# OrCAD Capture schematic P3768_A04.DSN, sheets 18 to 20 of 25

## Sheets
18 0007_DC JACK: size Custom
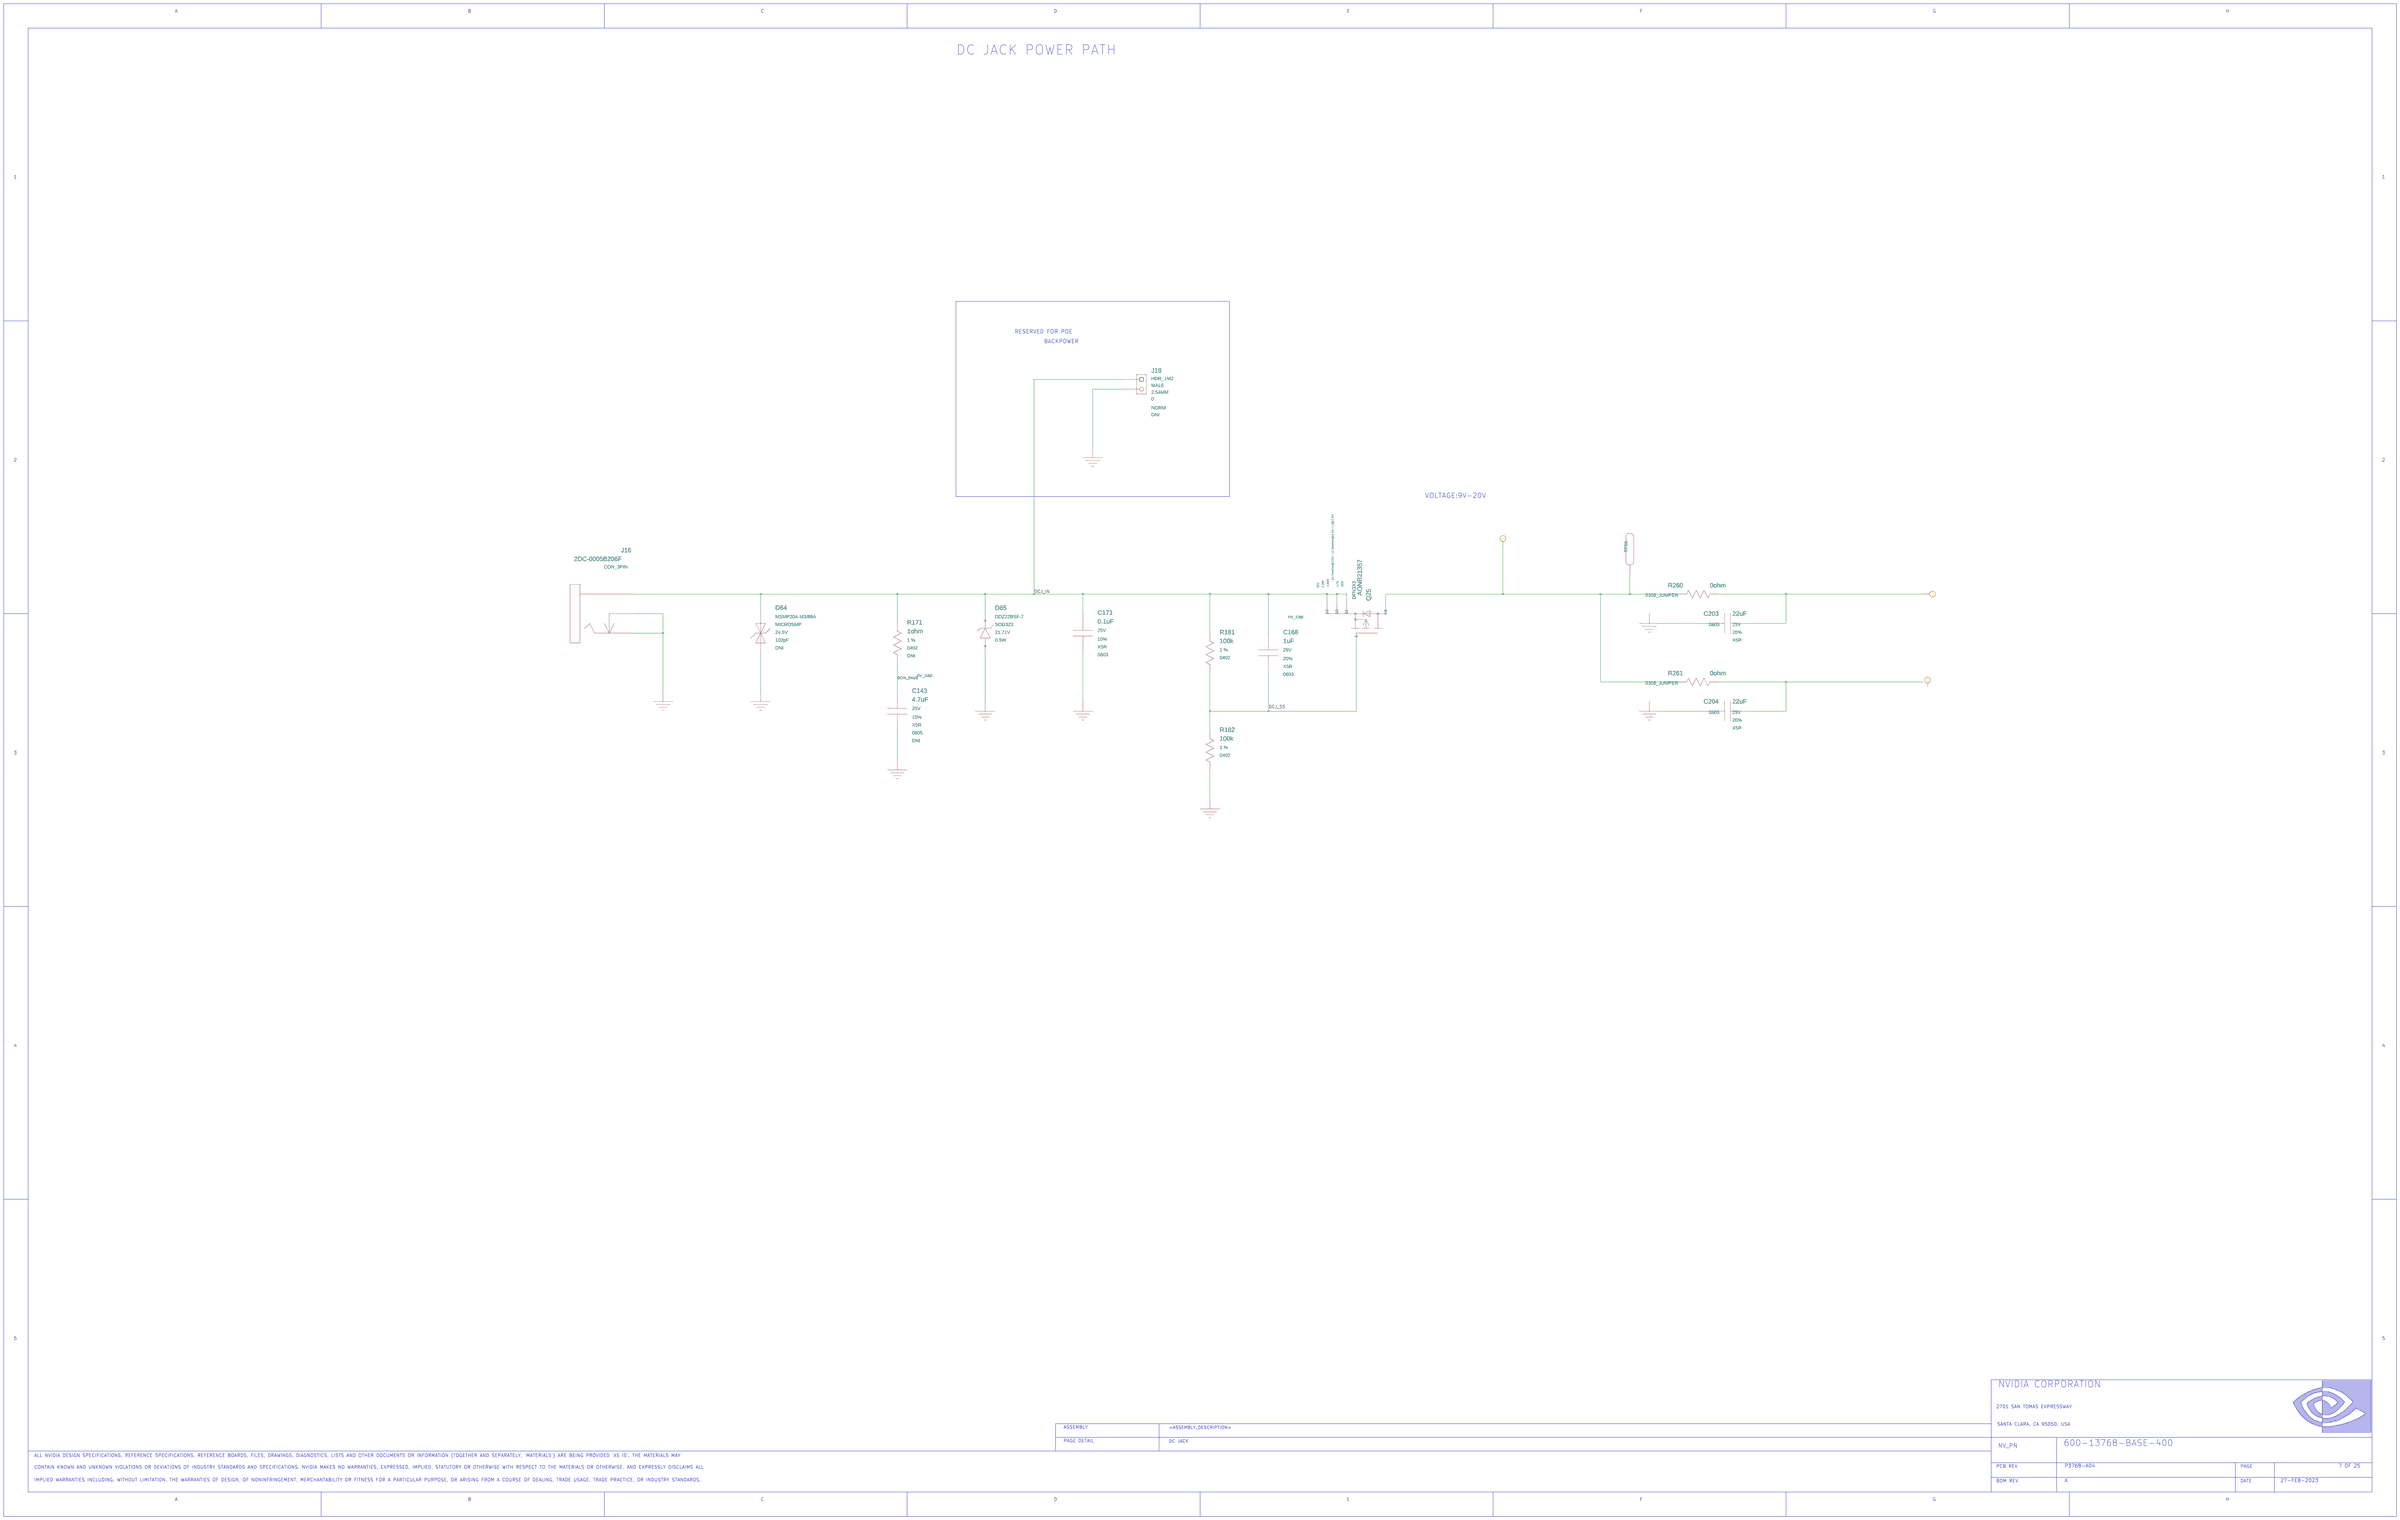
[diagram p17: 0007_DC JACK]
19 0006_SODIMM Connector 3_3: size Custom
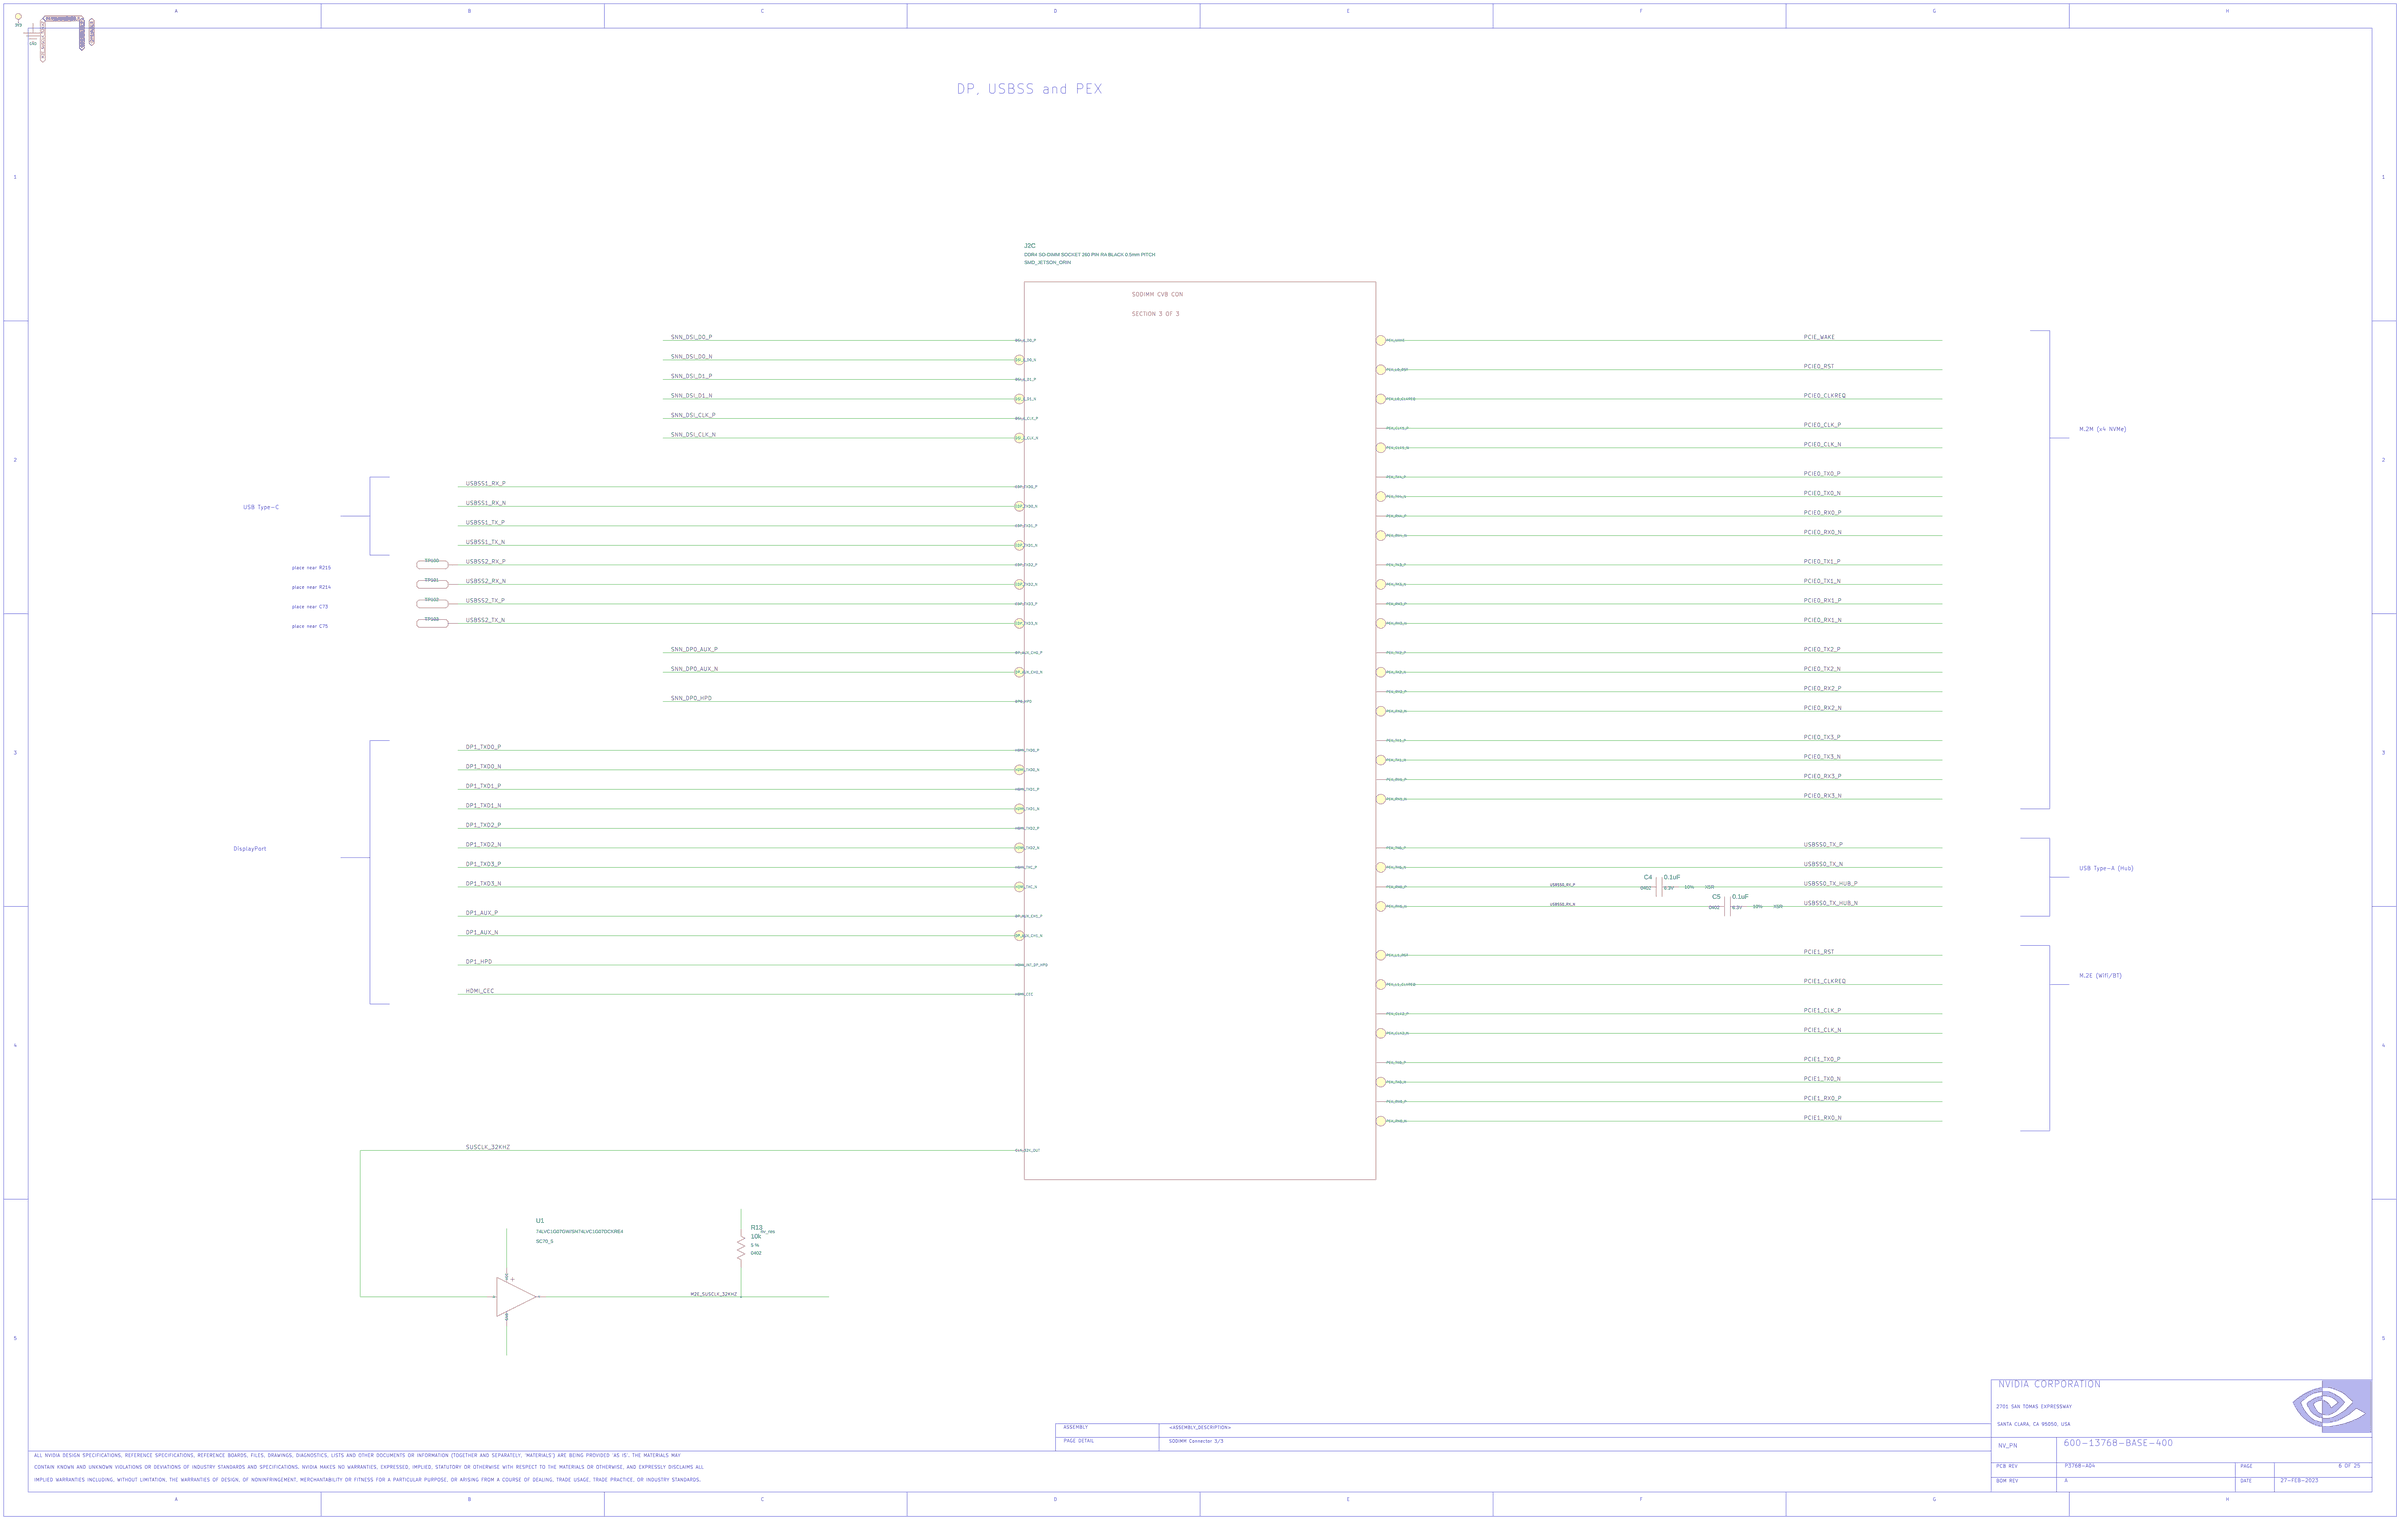
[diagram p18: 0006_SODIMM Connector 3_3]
20 0005_SODIMM Connector 2_3: size Custom
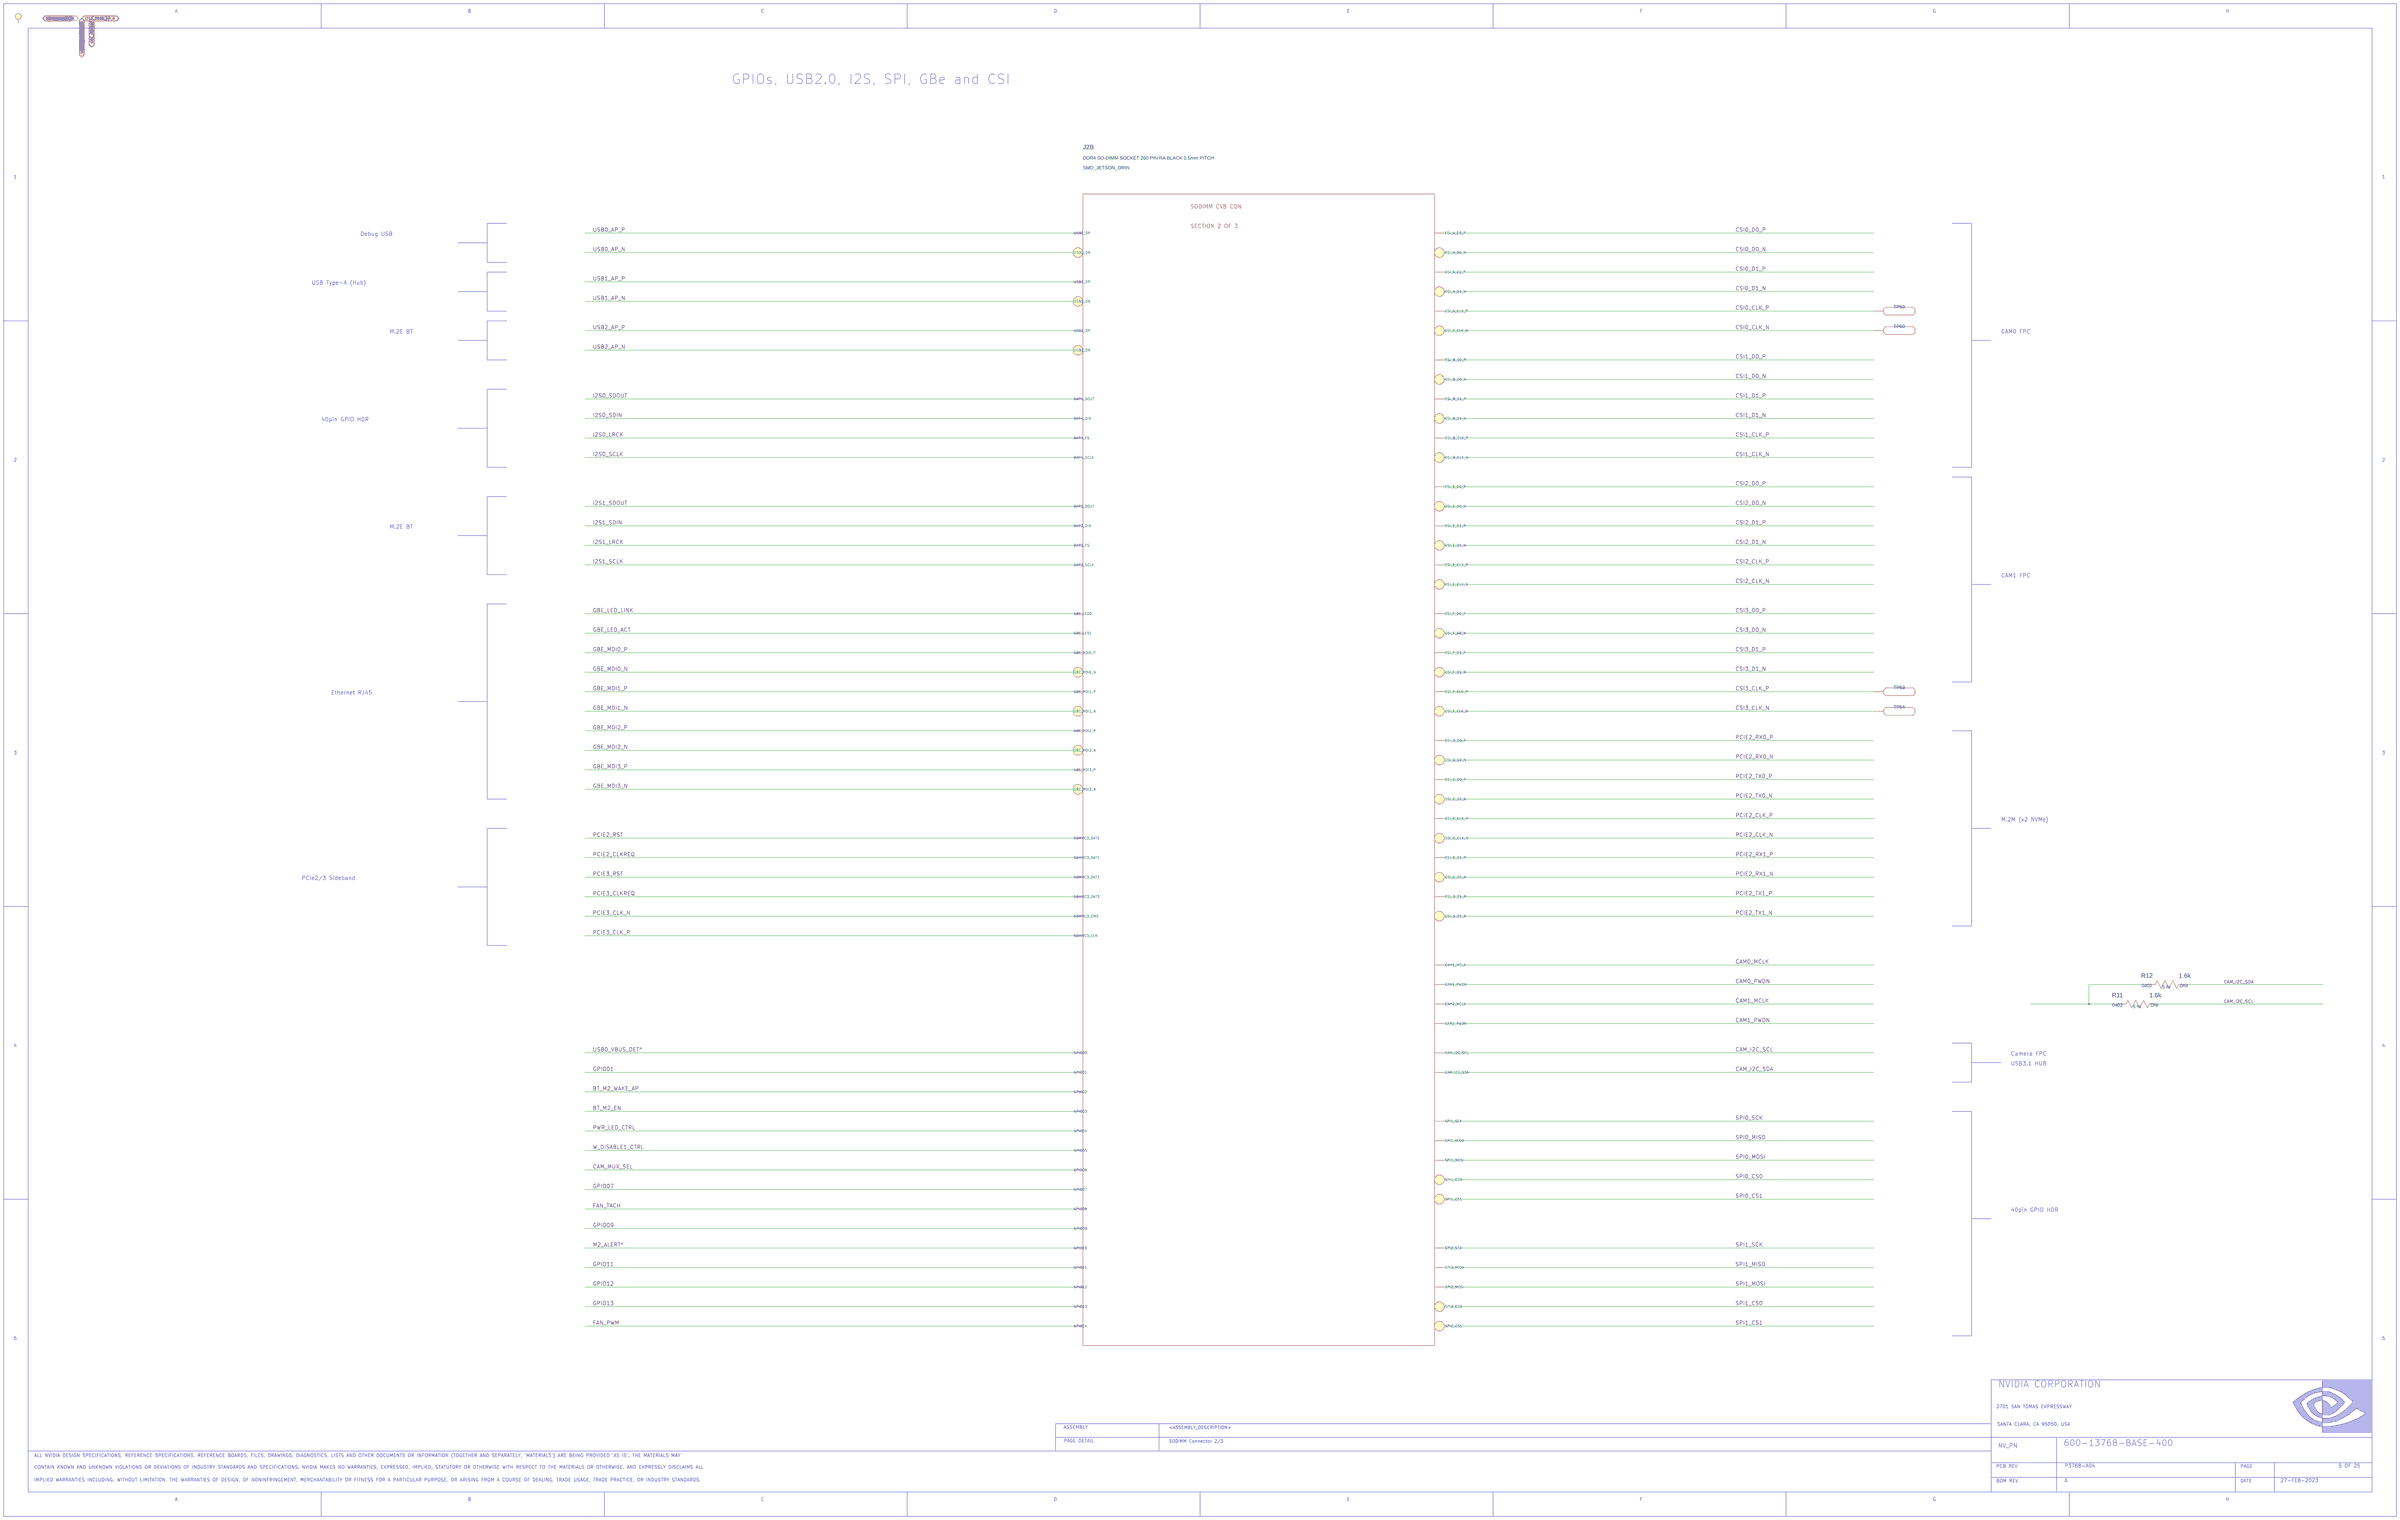
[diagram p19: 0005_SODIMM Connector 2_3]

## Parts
sheet 0005_SODIMM Connector 2_3
R11  1.6k  [0402]
R12  1.6k  [0402]
TP53  LABTESTPOINT  [LTPT025C]
TP54  LABTESTPOINT  [LTPT025C]
TP59  LABTESTPOINT  [LTPT025C]
TP60  LABTESTPOINT  [LTPT025C]
sheet 0006_SODIMM Connector 3_3
C4  0.1uF  [0402]
C5  0.1uF  [0402]
J2  CON_SODIMM_260  [CON_SODIMM_260_SMT_RA_F_P005]  (sections A,B,C)
R13  10k  [0402]
TP100  LABTESTPOINT  [LTPT025C]
TP101  LABTESTPOINT  [LTPT025C]
TP102  LABTESTPOINT  [LTPT025C]
TP103  LABTESTPOINT  [LTPT025C]
U1  U_BUF_OD  [SC70_5]
sheet 0007_DC JACK
C143  4.7uF  [0805U]
C168  1uF  [0603]
C171  0.1uF  [0603]
C203  22uF  [0805U]
C204  22uF  [0805U]
D64  D_ESD  [DIODE_SMD_025X013]
D65  D_ZENER  [DIODE_SMD_SOD323_C]
J16  CON_PWR_JACK  [CON_PWR_003_TH_RA_145X090_C]
J18  HDR_1X2  [CON_HDR_001X002_TH_ST_M_P025]
Q25  Q_FET_P_ENH  [DFET_SMD_032X033]
R171  1ohm  [0402]
R181  100k  [0402]
R182  100k  [0402]
R260  0ohm  [0603_BROADWISE_SHORT]
R261  0ohm  [0603_BROADWISE_SHORT]
TP56  LABTESTPOINT  [LTPT071C125D]

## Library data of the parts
R11 = R#1: ASSEMBLY: CVB_CONN; CDS_LIB: discrete; CDS_PART_NAME: R_0402-1.6K,5 %,62.5MW,195-0521-000; CDS_PHYS_PART_NAME: R_0402-1.6K,5 %,62.5MW,195-0521-000-1.6K,195-0521-000; CDS_SEC: 1; CHIPS_PART_NAME: R; DEVICE_TYPENAME: R_0402-16K5625MW195-0521-000-16K195-0521-000; DRAWING: @P3768_A04_LIB.P3768_A04(SCH_1):PAGE5; MAX_WATTAGE: 62.5mW; NV_PN: 195-0521-000; PATH: I130; PHYS_PAGE: 5; PSPICETEMPLATE: X^@REFDES  %1    %2   @NV_PN; ROT: 0; SEC: 1; SIGNAL_MODEL: nv_res; SKU: DNI; TOL: 5 %; VER: 1; XY: (-1200,2500)
R12 = R#1: ASSEMBLY: CVB_CONN; CDS_LIB: discrete; CDS_PART_NAME: R_0402-1.6K,5 %,62.5MW,195-0521-000; CDS_PHYS_PART_NAME: R_0402-1.6K,5 %,62.5MW,195-0521-000-1.6K,195-0521-000; CDS_SEC: 1; CHIPS_PART_NAME: R; DEVICE_TYPENAME: R_0402-16K5625MW195-0521-000-16K195-0521-000; DRAWING: @P3768_A04_LIB.P3768_A04(SCH_1):PAGE5; MAX_WATTAGE: 62.5mW; NV_PN: 195-0521-000; PATH: I129; PHYS_PAGE: 5; PSPICETEMPLATE: X^@REFDES  %1    %2   @NV_PN; ROT: 0; SEC: 1; SIGNAL_MODEL: nv_res; SKU: DNI; TOL: 5 %; VER: 1; XY: (-1050,2600)
TP53 = LABTESTPOINT: CDS_LIB: electro_mechanic; CDS_PART_NAME: LABTESTPOINT_PIN-TESTPOINT_0.25MM; CDS_PHYS_PART_NAME: LABTESTPOINT_PIN-TESTPOINT_0.25MM; CDS_SEC: 1; DEVICE_TYPENAME: LABTESTPOINT_PIN-TESTPOINT_025MM; DRAWING: @P3768_A04_LIB.P3768_A04(SCH_1):PAGE5; NV_NAME: TESTPOINT_0.25mm; PACK_TYPE: PIN; PATH: I246; PHYS_PAGE: 5; ROT: 0; SEC: 1; VER: 3; XY: (-2500,4100)
TP54 = LABTESTPOINT: CDS_LIB: electro_mechanic; CDS_PART_NAME: LABTESTPOINT_PIN-TESTPOINT_0.25MM; CDS_PHYS_PART_NAME: LABTESTPOINT_PIN-TESTPOINT_0.25MM; CDS_SEC: 1; DEVICE_TYPENAME: LABTESTPOINT_PIN-TESTPOINT_025MM; DRAWING: @P3768_A04_LIB.P3768_A04(SCH_1):PAGE5; NV_NAME: TESTPOINT_0.25mm; PACK_TYPE: PIN; PATH: I247; PHYS_PAGE: 5; ROT: 0; SEC: 1; VER: 3; XY: (-2500,4000)
TP59 = LABTESTPOINT: CDS_LIB: electro_mechanic; CDS_PART_NAME: LABTESTPOINT_PIN-TESTPOINT_0.25MM; CDS_PHYS_PART_NAME: LABTESTPOINT_PIN-TESTPOINT_0.25MM; CDS_SEC: 1; DEVICE_TYPENAME: LABTESTPOINT_PIN-TESTPOINT_025MM; DRAWING: @P3768_A04_LIB.P3768_A04(SCH_1):PAGE5; NV_NAME: TESTPOINT_0.25mm; PACK_TYPE: PIN; PATH: I248; PHYS_PAGE: 5; ROT: 0; SEC: 1; VER: 3; XY: (-2500,6050)
TP60 = LABTESTPOINT: CDS_LIB: electro_mechanic; CDS_PART_NAME: LABTESTPOINT_PIN-TESTPOINT_0.25MM; CDS_PHYS_PART_NAME: LABTESTPOINT_PIN-TESTPOINT_0.25MM; CDS_SEC: 1; DEVICE_TYPENAME: LABTESTPOINT_PIN-TESTPOINT_025MM; DRAWING: @P3768_A04_LIB.P3768_A04(SCH_1):PAGE5; NV_NAME: TESTPOINT_0.25mm; PACK_TYPE: PIN; PATH: I249; PHYS_PAGE: 5; ROT: 0; SEC: 1; VER: 3; XY: (-2500,5950)
C4 = C: ASSEMBLY: CVB_CONN; CDS_LIB: discrete; CDS_PART_NAME: C_0402-0.1UF,X5R,10%,6.3V,039-0007-000; CDS_PHYS_PART_NAME: C_0402-0.1UF,X5R,10%,6.3V,039-0007-000-0.1UF,039-0007-000; CDS_SEC: 1; DEVICE_TYPENAME: C_0402-01UFX5R1063V039-0007-000-01UF039-0007-000; DRAWING: @P3768_A04_LIB.P3768_A04(SCH_1):PAGE6; MAT: X5R; MAX_VOLTAGE: 6.3V; NV_PN: 039-0007-000; PATH: I36; PHYS_PAGE: 6; PSPICETEMPLATE: X^@REFDES  %1    %2   @NV_PN; ROT: 0; SEC: 1; SIGNAL_MODEL: nv_cap; TOL: 10%; VER: 2; XY: (-3650,3100)
C5 = C: ASSEMBLY: CVB_CONN; CDS_LIB: discrete; CDS_PART_NAME: C_0402-0.1UF,X5R,10%,6.3V,039-0007-000; CDS_PHYS_PART_NAME: C_0402-0.1UF,X5R,10%,6.3V,039-0007-000-0.1UF,039-0007-000; CDS_SEC: 1; DEVICE_TYPENAME: C_0402-01UFX5R1063V039-0007-000-01UF039-0007-000; DRAWING: @P3768_A04_LIB.P3768_A04(SCH_1):PAGE6; MAT: X5R; MAX_VOLTAGE: 6.3V; NV_PN: 039-0007-000; PATH: I34; PHYS_PAGE: 6; PSPICETEMPLATE: X^@REFDES  %1    %2   @NV_PN; ROT: 0; SEC: 1; SIGNAL_MODEL: nv_cap; TOL: 10%; VER: 2; XY: (-3300,3000)
J2 = CON_SODIMM_260: ANGLE: 90; ASSEMBLY: CVB_CONN; CDS_LIB: electro_mechanic; CDS_PART_NAME: CON_SODIMM_260_SMD_JETSON_ORIN-DDR4 SO-DIMM SOCKET 260 PIN RA BLACK 0.5MM PITCH,FEMALE,0.5MM,90,YES,YES,YES,NO,NO,25 V,0.5 A,080-1746-000; CDS_PHYS_PART_NAME: CON_SODIMM_260_SMD_JETSON_ORIN-DDR4 SO-DIMM SOCKET 260 PIN RA BLACK 0.5MM PITCH,FEMALE,0.5MM,90,YES,YES,YES,NO,NO,25 V,0.5 A,0B; CDS_SEC: 1; CaptureCellPackProp: CON_SODIMM_260A; DEVICE_TYPENAME: CON_SODIMM_260_SMD_JETSON_ORIN-DDR4SO-DIMMSOCKET260PINRABLACK05MMPITCHFEMALE05MM90YESYESYESNONO25V05A0B; DRAWING: @P3768_A04_LIB.P3768_A04(SCH_1):PAGE4; EMI_GROUND_TAB: NO; GENDER: FEMALE; LATCHING: YES; MAX_CURRENT: 0.5 A; MAX_VOLTAGE: 25 V; NV_NAME: DDR4 SO-DIMM SOCKET 260 PIN RA BLACK 0.5mm PITCH; NV_PN: 080-1746-000; PACK_TYPE: SMD_JETSON_ORIN; PATH: I62; PHYS_PAGE: 4; PITCH: 0.5mm; REFLOW: YES; ROT: 0; SEC: 1; SHIELDED: NO; SHROUDED: YES; VER: 10; XY: (-8650,3750); SEC_TYPE: SMD_JETSON_ORIN
R13 = R: ASSEMBLY: M2_WIFIBT; CDS_LIB: discrete; CDS_PART_NAME: R_0402-10K,5 %,62.5MW,195-0486-000; CDS_PHYS_PART_NAME: R_0402-10K,5 %,62.5MW,195-0486-000-10K,195-0486-000; CDS_SEC: 1; DEVICE_TYPENAME: R_0402-10K5625MW195-0486-000-10K195-0486-000; DRAWING: @P3768_A04_LIB.P3768_A04(SCH_1):PAGE6; MAX_WATTAGE: 62.5mW; NV_PN: 195-0486-000; PATH: I87; PHYS_PAGE: 6; PSPICETEMPLATE: X^@REFDES  %1    %2   @NV_PN; ROT: 0; SEC: 1; SIGNAL_MODEL: nv_res; TOL: 5 %; VER: 2; XY: (-8350,1250)
TP100 = LABTESTPOINT#1: CDS_LIB: electro_mechanic; CDS_PART_NAME: LABTESTPOINT_PIN-TESTPOINT_0.25MM; CDS_PHYS_PART_NAME: LABTESTPOINT_PIN-TESTPOINT_0.25MM; CDS_SEC: 1; DEVICE_TYPENAME: LABTESTPOINT_PIN-TESTPOINT_025MM; DRAWING: @P3768_A04_LIB.P3768_A04(SCH_1):PAGE6; NV_NAME: TESTPOINT_0.25mm; PACK_TYPE: PIN; PATH: I112; PHYS_PAGE: 6; ROT: 0; SEC: 1; VER: 1; XY: (-9850,4750)
TP101 = LABTESTPOINT#1: CDS_LIB: electro_mechanic; CDS_PART_NAME: LABTESTPOINT_PIN-TESTPOINT_0.25MM; CDS_PHYS_PART_NAME: LABTESTPOINT_PIN-TESTPOINT_0.25MM; CDS_SEC: 1; DEVICE_TYPENAME: LABTESTPOINT_PIN-TESTPOINT_025MM; DRAWING: @P3768_A04_LIB.P3768_A04(SCH_1):PAGE6; NV_NAME: TESTPOINT_0.25mm; PACK_TYPE: PIN; PATH: I113; PHYS_PAGE: 6; ROT: 0; SEC: 1; VER: 1; XY: (-9850,4650)
TP102 = LABTESTPOINT#1: CDS_LIB: electro_mechanic; CDS_PART_NAME: LABTESTPOINT_PIN-TESTPOINT_0.25MM; CDS_PHYS_PART_NAME: LABTESTPOINT_PIN-TESTPOINT_0.25MM; CDS_SEC: 1; DEVICE_TYPENAME: LABTESTPOINT_PIN-TESTPOINT_025MM; DRAWING: @P3768_A04_LIB.P3768_A04(SCH_1):PAGE6; NV_NAME: TESTPOINT_0.25mm; PACK_TYPE: PIN; PATH: I114; PHYS_PAGE: 6; ROT: 0; SEC: 1; VER: 1; XY: (-9850,4550)
TP103 = LABTESTPOINT#1: CDS_LIB: electro_mechanic; CDS_PART_NAME: LABTESTPOINT_PIN-TESTPOINT_0.25MM; CDS_PHYS_PART_NAME: LABTESTPOINT_PIN-TESTPOINT_0.25MM; CDS_SEC: 1; DEVICE_TYPENAME: LABTESTPOINT_PIN-TESTPOINT_025MM; DRAWING: @P3768_A04_LIB.P3768_A04(SCH_1):PAGE6; NV_NAME: TESTPOINT_0.25mm; PACK_TYPE: PIN; PATH: I115; PHYS_PAGE: 6; ROT: 0; SEC: 1; VER: 1; XY: (-9850,4450)
U1 = U_BUF_OD: ASSEMBLY: M2_WIFIBT; CDS_LIB: logic; CDS_PART_NAME: U_BUF_OD_SC70_5-74LVC1G07GW/SN74LVC1G07DCKRE4,BUFFER - OPEN DRAIN,115-0138-000; CDS_PHYS_PART_NAME: U_BUF_OD_SC70_5-74LVC1G07GW/SN74LVC1G07DCKRE4,BUFFER - OPEN DRAIN,115-0138-000-115-0138-000; CDS_SEC: 1; DEVICE_TYPENAME: U_BUF_OD_SC70_5-74LVC1G07GWSN74LVC1G07DCKRE4BUFFER-OPENDRAIN115-0138-000-115-0138-000; DRAWING: @P3768_A04_LIB.P3768_A04(SCH_1):PAGE6; FUNCTION: Buffer - Open Drain; NV_NAME: 74LVC1G07GW/SN74LVC1G07DCKRE4; NV_PN: 115-0138-000; PATH: I85; PHYS_PAGE: 6; ROT: 0; SEC: 1; VER: 1; XY: (-9500,1000)
C143 = C#1: ASSEMBLY: DCJACK; CDS_LIB: discrete; CDS_PART_NAME: C_0805-4.7UF,X5R,10%,25V,032-1141-000; CDS_PHYS_PART_NAME: C_0805-4.7UF,X5R,10%,25V,032-1141-000-032-1141-000,4.7UF; CDS_SEC: 1; CHIPS_PART_NAME: C; DEVICE_TYPENAME: C_0805-47UFX5R1025V032-1141-000-032-1141-00047UF; DRAWING: @P3768_A04_LIB.P3768_A04(SCH_1):PAGE7; IMPLEMENTATION_TYPE: X^@REFDES  %1    %2   @NV_PN; MAT: X5R; MAX_VOLTAGE: 25V; NV_PN: 032-1141-000; PACK_TYPE: 0805; PATH: I518; PHYS_PAGE: 7; PSPICETEMPLATE: Pspice Model; ROT: 0; SEC: 1; SIGNAL_MODEL: nv_cap; SKU: DNI; TOL: 10%; VER: 1; XY: (-7550,4000)
C168 = C#1: ASSEMBLY: DCJACK; CDS_LIB: discrete; CDS_PART_NAME: C_0603-1UF,X5R,20%,25V,032-0882-000; CDS_PHYS_PART_NAME: C_0603-1UF,X5R,20%,25V,032-0882-000-032-0882-000,1UF; CDS_SEC: 1; CHIPS_PART_NAME: C; DEVICE_TYPENAME: C_0603-1UFX5R2025V032-0882-000-032-0882-0001UF; DRAWING: @P3768_A04_LIB.P3768_A04(SCH_1):PAGE7; IMPLEMENTATION_TYPE: X^@REFDES  %1    %2   @NV_PN; MAT: X5R; MAX_VOLTAGE: 25V; NV_PN: 032-0882-000; PATH: I530; PHYS_PAGE: 7; PSPICETEMPLATE: Pspice Model; ROT: 0; SEC: 1; SIGNAL_MODEL: nv_cap; TOL: 20%; VER: 1; XY: (-5650,4300)
C171 = C#1: ASSEMBLY: DCJACK; CDS_LIB: discrete; CDS_PART_NAME: C_0603-0.1UF,X5R,10%,25V,039-0044-000; CDS_PHYS_PART_NAME: C_0603-0.1UF,X5R,10%,25V,039-0044-000-0.1UF,039-0044-000; CDS_SEC: 1; CHIPS_PART_NAME: C; DEVICE_TYPENAME: C_0603-01UFX5R1025V039-0044-000-01UF039-0044-000; DRAWING: @P3768_A04_LIB.P3768_A04(SCH_1):PAGE7; MAT: X5R; MAX_VOLTAGE: 25V; NV_PN: 039-0044-000; PATH: I527; PHYS_PAGE: 7; PSPICETEMPLATE: X^@REFDES  %1    %2   @NV_PN; ROT: 0; SEC: 1; SIGNAL_MODEL: nv_cap; TOL: 10%; VER: 1; XY: (-6600,4400)
C203 = C: ASSEMBLY: DCJACK; CDS_LIB: discrete; CDS_PART_NAME: C_0805-22UF,X5R,20%,25V,032-1308-000; CDS_PHYS_PART_NAME: C_0805-22UF,X5R,20%,25V,032-1308-000-032-1308-000,22UF; CDS_SEC: 1; DEVICE_TYPENAME: C_0805-22UFX5R2025V032-1308-000-032-1308-00022UF; DRAWING: @P3768_A04_LIB.P3768_A04(SCH_1):PAGE7; MAT: X5R; MAX_VOLTAGE: 25V; NV_PN: 032-1308-000; PACK_TYPE: 0805; PATH: I298; PHYS_PAGE: 7; ROT: 0; SEC: 1; SIGNAL_MODEL: nv_cap; TOL: 20%; VER: 2; XY: (-3300,4450)
C204 = C: ASSEMBLY: DCJACK; CDS_LIB: discrete; CDS_PART_NAME: C_0805-22UF,X5R,20%,25V,032-1308-000; CDS_PHYS_PART_NAME: C_0805-22UF,X5R,20%,25V,032-1308-000-032-1308-000,22UF; CDS_SEC: 1; DEVICE_TYPENAME: C_0805-22UFX5R2025V032-1308-000-032-1308-00022UF; DRAWING: @P3768_A04_LIB.P3768_A04(SCH_1):PAGE7; MAT: X5R; MAX_VOLTAGE: 25V; NV_PN: 032-1308-000; PACK_TYPE: 0805; PATH: I300; PHYS_PAGE: 7; ROT: 0; SEC: 1; SIGNAL_MODEL: nv_cap; TOL: 20%; VER: 2; XY: (-3300,4000)
D64 = D_ESD: ASSEMBLY: DCJACK; BREAKDOWN_VOLTAGE_MIN_TYP: 22.2V; CAPACITANCE_MAX_TYP: 102pF; CDS_LIB: discrete; CDS_PART_NAME: D_ESD_MICROSMP-MSMP20A-M3/89A,1 LINE,UNI-DIRECTIONAL,24.5V,1UA,22.2V,42.8V@23.4A,102PF,090-0378-000; CDS_PHYS_PART_NAME: D_ESD_MICROSMP-MSMP20A-M3/89A,1 LINE,UNI-DIRECTIONAL,24.5V,1UA,22.2V,42.8V@23.4A,102PF,090-0378-000-090-0378-000; CDS_SEC: 1; CLAMPING_VOLTAGE: 42.8V@23.4A; CONFIGURATION: 1 Line; DEVICE_TYPENAME: D_ESD_MICROSMP-MSMP20A-M389A1LINEUNI-DIRECTIONAL245V1UA222V428V234A102PF090-0378-000-090-0378-000; DRAWING: @P3768_A04_LIB.P3768_A04(SCH_1):PAGE7; MAX_REVERSE_LEAKAGE_CURRENT: 1uA; MAX_REVERSE_VOLTAGE: 24.5V; NV_NAME: MSMP20A-M3/89A; NV_PN: 090-0378-000; PACK_TYPE: MICROSMP; PATH: I522; PHYS_PAGE: 7; POLARITY: Uni-Directional; ROT: 0; SEC: 1; SKU: DNI; VER: 2; XY: (-8250,4400)
D65 = D_ZENER: ASSEMBLY: DCJACK; CDS_LIB: discrete; CDS_PART_NAME: D_ZENER_SOD323-DDZ22BSF-7,21.71V,5MA,0.9V@10MA,0.5W,090-0377-000; CDS_PHYS_PART_NAME: D_ZENER_SOD323-DDZ22BSF-7,21.71V,5MA,0.9V@10MA,0.5W,090-0377-000-090-0377-000; CDS_SEC: 1; CONTINUOUS_CURRENT: 0.5W; DEVICE_TYPENAME: D_ZENER_SOD323-DDZ22BSF-72171V5MA09V10MA05W090-0377-000-090-0377-000; DRAWING: @P3768_A04_LIB.P3768_A04(SCH_1):PAGE7; FORWARD_VOLTAGE: 0.9V@10mA; MAX_CURRENT: 5mA; MAX_VOLTAGE: 21.71V; NV_NAME: DDZ22BSF-7; NV_PN: 090-0377-000; PACK_TYPE: SOD323; PATH: I525; PHYS_PAGE: 7; ROT: 0; SEC: 1; VER: 2; XY: (-7100,4400)
J16 = CON_PWR_JACK: ANGLE: 90; ASSEMBLY: DCJACK; CDS_LIB: electro_mechanic; CDS_PART_NAME: CON_PWR_JACK_CON_3PIN-2DC-0005B206F,FEMALE,N/A,90,NO,YES,N/A,N/A,NO,24 V,5 A,064-0437-000; CDS_PHYS_PART_NAME: CON_PWR_JACK_CON_3PIN-2DC-0005B206F,FEMALE,N/A,90,NO,YES,N/A,N/A,NO,24 V,5 A,064-0437-000-064-0437-000; CDS_SEC: 1; DEVICE_TYPENAME: CON_PWR_JACK_CON_3PIN-2DC-0005B206FFEMALENA90NOYESNANANO24V5A064-0437-000-064-0437-000; DRAWING: @P3768_A04_LIB.P3768_A04(SCH_1):PAGE7; EMI_GROUND_TAB: N/A; GENDER: FEMALE; LATCHING: N/A; MAX_CURRENT: 5 A; MAX_VOLTAGE: 24 V; NV_NAME: 2DC-0005B206F; NV_PN: 064-0437-000; PACK_TYPE: CON_3PIN; PATH: I515; PHYS_PAGE: 7; PITCH: N/A; REFLOW: NO; ROT: 2; SEC: 1; SEC_TYPE: CON_3PIN; SHIELDED: NO; SHROUDED: YES; VER: 1; XY: (-9200,4600)
J18 = HDR_1X2: ANGLE: 0; ASSEMBLY: DCJACK; CDS_LIB: electro_mechanic; CDS_PART_NAME: HDR_1X2_NORM-HDR_1M2,MALE,2.54MM,0,NO,NO,NO,250V,3A,074-0117-000; CDS_PHYS_PART_NAME: HDR_1X2_NORM-HDR_1M2,MALE,2.54MM,0,NO,NO,NO,250V,3A,074-0117-000-074-0117-000; CDS_SEC: 1; DEVICE_TYPENAME: HDR_1X2_NORM-HDR_1M2MALE254MM0NONONO250V3A074-0117-000-074-0117-000; DRAWING: @P3768_A04_LIB.P3768_A04(SCH_1):PAGE7; GENDER: MALE; LATCHING: NO; MAX_CURRENT: 3A; MAX_VOLTAGE: 250V; NV_NAME: HDR_1M2; NV_PN: 074-0117-000; PACK_TYPE: NORM; PATH: I531; PHYS_PAGE: 7; PITCH: 2.54MM; REFLOW: NO; ROT: 0; SEC: 1; SHROUDED: NO; SKU: DNI; VER: 1; XY: (-6300,5700)
Q25 = Q_FET_P_ENH: ASSEMBLY: DCJACK; CDS_LIB: discrete; CDS_PART_NAME: Q_FET_P_ENH_DFN3X3-AONR21357,-30V,10.7MOHM@10V / 12.3MOHM@4.5V / [ ]@2.5V,-17A,-136A,25V,3.2W,70NC@10V / 35NC@4.5V / [ ]@2.5V,300-1070-000; CDS_PHYS_PART_NAME: Q_FET_P_ENH_DFN3X3-AONR21357,-30V,10.7MOHM@10V / 12.3MOHM@4.5V / [ ]@2.5V,-17A,-136A,25V,3.2W,70NC@10V / 35NC@4.5V / [ ]@2.5V,B; CDS_SEC: 1; CONTINUOUS_CURRENT: -17A; DEVICE_TYPENAME: Q_FET_P_ENH_DFN3X3-AONR21357-30V107MOHM10V123MOHM45V25V-17A-136A25V32W70NC10V35NC45V25VB; DRAWING: @P3768_A04_LIB.P3768_A04(SCH_1):PAGE7; MAX_CURRENT: -136A; MAX_VOLTAGE: -30V; MAX_WATTAGE: 3.2W; NV_NAME: AONR21357; NV_PN: 300-1070-000; PACK_TYPE: DFN3X3; PATH: I532; PHYS_PAGE: 7; Q_G: 70nC@10V / 35nC@4.5V / [ ]@2.5V; ROT: 7; R_DS_ON: 10.7mohm@10V / 12.3mohm@4.5V / [ ]@2.5V; SEC: 1; VER: 8; V_BE_GS: 25V; XY: (-5150,4450)
R171 = R: ASSEMBLY: DCJACK; CDS_LIB: discrete; CDS_PART_NAME: R_0402-1OHM,1 %,62.5MW,195-2682-000; CDS_PHYS_PART_NAME: R_0402-1OHM,1 %,62.5MW,195-2682-000-195-2682-000,1OHM; CDS_SEC: 1; DEVICE_TYPENAME: R_0402-1OHM1625MW195-2682-000-195-2682-0001OHM; DRAWING: @P3768_A04_LIB.P3768_A04(SCH_1):PAGE7; MAX_WATTAGE: 62.5mW; NV_PN: 195-2682-000; PATH: I523; PHYS_PAGE: 7; PSPICETEMPLATE: X^@REFDES  %1    %2   @NV_PN; ROT: 0; SEC: 1; SIGNAL_MODEL: nv_res; SKU: DNI; TOL: 1 %; VER: 2; XY: (-7550,4350)
R181 = R: ASSEMBLY: DCJACK; CDS_LIB: discrete; CDS_PART_NAME: R_0402-100K,1 %,62.5MW,195-0005-000; CDS_PHYS_PART_NAME: R_0402-100K,1 %,62.5MW,195-0005-000-100K,195-0005-000; CDS_SEC: 1; DEVICE_TYPENAME: R_0402-100K1625MW195-0005-000-100K195-0005-000; DRAWING: @P3768_A04_LIB.P3768_A04(SCH_1):PAGE7; MAX_WATTAGE: 62.5mW; NV_PN: 195-0005-000; PATH: I529; PHYS_PAGE: 7; PSPICETEMPLATE: X^@REFDES  %1    %2   @NV_PN; ROT: 0; SEC: 1; SIGNAL_MODEL: nv_res; TOL: 1 %; VER: 2; XY: (-5950,4300)
R182 = R: ASSEMBLY: DCJACK; CDS_LIB: discrete; CDS_PART_NAME: R_0402-100K,1 %,62.5MW,195-0005-000; CDS_PHYS_PART_NAME: R_0402-100K,1 %,62.5MW,195-0005-000-100K,195-0005-000; CDS_SEC: 1; DEVICE_TYPENAME: R_0402-100K1625MW195-0005-000-100K195-0005-000; DRAWING: @P3768_A04_LIB.P3768_A04(SCH_1):PAGE7; MAX_WATTAGE: 62.5mW; NV_PN: 195-0005-000; PATH: I520; PHYS_PAGE: 7; PSPICETEMPLATE: X^@REFDES  %1    %2   @NV_PN; ROT: 0; SEC: 1; SIGNAL_MODEL: nv_res; TOL: 1 %; VER: 2; XY: (-5950,3800)
R260 = R#1: ASSEMBLY: DCJACK; CDS_LIB: discrete; CDS_PART_NAME: R_0306_JUMPER-0OHM,0.05 OHM,0.1W,195-3883-000; CDS_PHYS_PART_NAME: R_0306_JUMPER-0OHM,0.05 OHM,0.1W,195-3883-000-0OHM,195-3883-000; CDS_SEC: 1; CHIPS_PART_NAME: R; DEVICE_TYPENAME: R_0306_JUMPER-0OHM005OHM01W195-3883-000-0OHM195-3883-000; DRAWING: @P3768_A04_LIB.P3768_A04(SCH_1):PAGE7; MAX_WATTAGE: 0.1W; NV_PN: 195-3883-000; PACK_TYPE: 0306_JUMPER; PATH: I534; PHYS_PAGE: 7; ROT: 0; SEC: 1; SIGNAL_MODEL: nv_res; TOL: 0.05 ohm; VER: 1; XY: (-3450,4600)
R261 = R#1: ASSEMBLY: DCJACK; CDS_LIB: discrete; CDS_PART_NAME: R_0306_JUMPER-0OHM,0.05 OHM,0.1W,195-3883-000; CDS_PHYS_PART_NAME: R_0306_JUMPER-0OHM,0.05 OHM,0.1W,195-3883-000-0OHM,195-3883-000; CDS_SEC: 1; CHIPS_PART_NAME: R; DEVICE_TYPENAME: R_0306_JUMPER-0OHM005OHM01W195-3883-000-0OHM195-3883-000; DRAWING: @P3768_A04_LIB.P3768_A04(SCH_1):PAGE7; MAX_WATTAGE: 0.1W; NV_PN: 195-3883-000; PACK_TYPE: 0306_JUMPER; PATH: I535; PHYS_PAGE: 7; ROT: 0; SEC: 1; SIGNAL_MODEL: nv_res; TOL: 0.05 ohm; VER: 1; XY: (-3450,4150)
TP56 = LABTESTPOINT#2: CDS_LIB: electro_mechanic; CDS_PART_NAME: LABTESTPOINT_B28-LABTESTPOINT; CDS_PHYS_PART_NAME: LABTESTPOINT_B28-LABTESTPOINT; CDS_SEC: 1; DEVICE_TYPENAME: LABTESTPOINT_B28-LABTESTPOINT; DRAWING: @P3768_A04_LIB.P3768_A04(SCH_1):PAGE7; PACK_TYPE: B28; PATH: I533; PHYS_PAGE: 7; ROT: 0; SEC: 1; VER: 4; XY: (-3800,4750)

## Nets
GND: C143.2 C171.2 C203.1 C204.1 D64.2 D65.2(A) J16.2 J16.3 J18.2 R182.2 U1.3(GND) ; also on sheet 1 2 3 4 5 6 7 8 9 10 11 12 13 14 15 16 17 21 25
VDD_1V8: U1.5(VCC) ; also on sheet 1 2 3 5 8 12 14 21
VDD_3V3_SYS: R11.1 R12.1 R13.1 ; also on sheet 1 2 3 4 5 6 7 8 11 12 14 15 21
VDD_CVB: C203.2 R260.2 ; also on sheet 15 16
VDD_DCIN: Q25.5(D) R260.1 R261.1 TP56.1 ; also on sheet 13
VDD_HV: C204.2 R261.2 ; also on sheet 17
BT_M2_EN: J2.126(GPIO03) ; also on sheet 5
BT_M2_WAKE_AP: J2.124(GPIO02) ; also on sheet 5
CAM0_MCLK: J2.116(CAM1_MCLK) ; also on sheet 7
CAM0_PWDN: J2.114(CAM1_PWDN) ; also on sheet 7
CAM1_MCLK: J2.122(CAM2_MCLK) ; also on sheet 7
CAM1_PWDN: J2.120(CAM2_PWDN) ; also on sheet 7
CAM_I2C_SCL: J2.213(CAM_I2C_SCL) R11.2 ; also on sheet 7 11
CAM_I2C_SDA: J2.215(CAM_I2C_SDA) R12.2 ; also on sheet 7 11
CAM_MUX_SEL: J2.130(GPIO06) ; also on sheet 7
CSI0_CLK_N: J2.10(CSI_A_CLK_N) TP60.1
CSI0_CLK_P: J2.12(CSI_A_CLK_P) TP59.1
CSI0_D0_N: J2.4(CSI_A_D0_N) ; also on sheet 7
CSI0_D0_P: J2.6(CSI_A_D0_P) ; also on sheet 7
CSI0_D1_N: J2.16(CSI_A_D1_N) ; also on sheet 7
CSI0_D1_P: J2.18(CSI_A_D1_P) ; also on sheet 7
CSI1_CLK_N: J2.9(CSI_B_CLK_N) ; also on sheet 7
CSI1_CLK_P: J2.11(CSI_B_CLK_P) ; also on sheet 7
CSI1_D0_N: J2.3(CSI_B_D0_N) ; also on sheet 7
CSI1_D0_P: J2.5(CSI_B_D0_P) ; also on sheet 7
CSI1_D1_N: J2.15(CSI_B_D1_N) ; also on sheet 7
CSI1_D1_P: J2.17(CSI_B_D1_P) ; also on sheet 7
CSI2_CLK_N: J2.28(CSI_E_CLK_N) ; also on sheet 7
CSI2_CLK_P: J2.30(CSI_E_CLK_P) ; also on sheet 7
CSI2_D0_N: J2.22(CSI_E_D0_N) ; also on sheet 7
CSI2_D0_P: J2.24(CSI_E_D0_P) ; also on sheet 7
CSI2_D1_N: J2.34(CSI_E_D1_N) ; also on sheet 7
CSI2_D1_P: J2.36(CSI_E_D1_P) ; also on sheet 7
CSI3_CLK_N: J2.27(CSI_F_CLK_N) TP54.1
CSI3_CLK_P: J2.29(CSI_F_CLK_P) TP53.1
CSI3_D0_N: J2.21(CSI_F_D0_N) ; also on sheet 7
CSI3_D0_P: J2.23(CSI_F_D0_P) ; also on sheet 7
CSI3_D1_N: J2.33(CSI_F_D1_N) ; also on sheet 7
CSI3_D1_P: J2.35(CSI_F_D1_P) ; also on sheet 7
DCIN_SNUB: C143.1 R171.2
DCJ_IN: C168.1 C171.1 D64.1 D65.1(K) J16.1 J18.1 Q25.1(S1) Q25.2(S2) Q25.3(S3) R171.1 R181.1
DCJ_SS: C168.2 Q25.4(G) R181.2 R182.1
DP1_AUX_N: J2.98(DP_AUX_CH1_N) ; also on sheet 8
DP1_AUX_P: J2.100(DP_AUX_CH1_P) ; also on sheet 8
DP1_HPD: J2.96(HDMI_INT_DP_HPD) ; also on sheet 8
DP1_TXD0_N: J2.63(HDMI_TXD0_N) ; also on sheet 8
DP1_TXD0_P: J2.65(HDMI_TXD0_P) ; also on sheet 8
DP1_TXD1_N: J2.69(HDMI_TXD1_N) ; also on sheet 8
DP1_TXD1_P: J2.71(HDMI_TXD1_P) ; also on sheet 8
DP1_TXD2_N: J2.75(HDMI_TXD2_N) ; also on sheet 8
DP1_TXD2_P: J2.77(HDMI_TXD2_P) ; also on sheet 8
DP1_TXD3_N: J2.81(HDMI_TXC_N) ; also on sheet 8
DP1_TXD3_P: J2.83(HDMI_TXC_P) ; also on sheet 8
FAN_PWM: J2.230(GPIO14) ; also on sheet 1
FAN_TACH: J2.208(GPIO08) ; also on sheet 1
GBE_LED_ACT: J2.194(GBE_LED1) ; also on sheet 6
GBE_LED_LINK: J2.188(GBE_LED0) ; also on sheet 6
GBE_MDI0_N: J2.184(GBE_MDI0_N) ; also on sheet 6
GBE_MDI0_P: J2.186(GBE_MDI0_P) ; also on sheet 6
GBE_MDI1_N: J2.190(GBE_MDI1_N) ; also on sheet 6
GBE_MDI1_P: J2.192(GBE_MDI1_P) ; also on sheet 6
GBE_MDI2_N: J2.196(GBE_MDI2_N) ; also on sheet 6
GBE_MDI2_P: J2.198(GBE_MDI2_P) ; also on sheet 6
GBE_MDI3_N: J2.202(GBE_MDI3_N) ; also on sheet 6
GBE_MDI3_P: J2.204(GBE_MDI3_P) ; also on sheet 6
GPIO01: J2.118(GPIO01) ; also on sheet 2
GPIO07: J2.206(GPIO07) ; also on sheet 2
GPIO09: J2.211(GPIO09) ; also on sheet 2
GPIO11: J2.216(GPIO11) ; also on sheet 2
GPIO12: J2.218(GPIO12) ; also on sheet 2
GPIO13: J2.228(GPIO13) ; also on sheet 2
HDMI_CEC: J2.94(HDMI_CEC) ; also on sheet 8
I2S0_LRCK: J2.197(DAP4_FS) ; also on sheet 2
I2S0_SCLK: J2.199(DAP4_SCLK) ; also on sheet 2
I2S0_SDIN: J2.195(DAP4_DIN) ; also on sheet 2
I2S0_SDOUT: J2.193(DAP4_DOUT) ; also on sheet 2
I2S1_LRCK: J2.224(DAP3_FS) ; also on sheet 5
I2S1_SCLK: J2.226(DAP3_SCLK) ; also on sheet 5
I2S1_SDIN: J2.222(DAP3_DIN) ; also on sheet 5
I2S1_SDOUT: J2.220(DAP3_DOUT) ; also on sheet 5
M2_ALERT*: J2.212(GPIO10) ; also on sheet 3
M2E_SUSCLK_32KHZ: R13.2 U1.4(Y) ; also on sheet 5
PCIE0_CLK_N: J2.160(PEX_CLK1_N) ; also on sheet 4
PCIE0_CLK_P: J2.162(PEX_CLK1_P) ; also on sheet 4
PCIE0_CLKREQ: J2.180(PEX_L0_CLKREQ) ; also on sheet 4
PCIE0_RST: J2.181(PEX_L0_RST) ; also on sheet 4
PCIE0_RX0_N: J2.131(PEX_RX4_N) ; also on sheet 4
PCIE0_RX0_P: J2.133(PEX_RX4_P) ; also on sheet 4
PCIE0_RX1_N: J2.137(PEX_RX3_N) ; also on sheet 4
PCIE0_RX1_P: J2.139(PEX_RX3_P) ; also on sheet 4
PCIE0_RX2_N: J2.149(PEX_RX2_N) ; also on sheet 4
PCIE0_RX2_P: J2.151(PEX_RX2_P) ; also on sheet 4
PCIE0_RX3_N: J2.155(PEX_RX1_N) ; also on sheet 4
PCIE0_RX3_P: J2.157(PEX_RX1_P) ; also on sheet 4
PCIE0_TX0_N: J2.134(PEX_TX4_N) ; also on sheet 4
PCIE0_TX0_P: J2.136(PEX_TX4_P) ; also on sheet 4
PCIE0_TX1_N: J2.140(PEX_TX3_N) ; also on sheet 4
PCIE0_TX1_P: J2.142(PEX_TX3_P) ; also on sheet 4
PCIE0_TX2_N: J2.148(PEX_TX2_N) ; also on sheet 4
PCIE0_TX2_P: J2.150(PEX_TX2_P) ; also on sheet 4
PCIE0_TX3_N: J2.154(PEX_TX1_N) ; also on sheet 4
PCIE0_TX3_P: J2.156(PEX_TX1_P) ; also on sheet 4
PCIE1_CLK_N: J2.173(PEX_CLK2_N) ; also on sheet 5
PCIE1_CLK_P: J2.175(PEX_CLK2_P) ; also on sheet 5
PCIE1_CLKREQ: J2.182(PEX_L1_CLKREQ) ; also on sheet 5
PCIE1_RST: J2.183(PEX_L1_RST) ; also on sheet 5
PCIE1_RX0_N: J2.167(PEX_RX0_N) ; also on sheet 5
PCIE1_RX0_P: J2.169(PEX_RX0_P) ; also on sheet 5
PCIE1_TX0_N: J2.172(PEX_TX0_N) ; also on sheet 5
PCIE1_TX0_P: J2.174(PEX_TX0_P) ; also on sheet 5
PCIE2_CLK_N: J2.52(CSI_C_CLK_N) ; also on sheet 3
PCIE2_CLK_P: J2.54(CSI_C_CLK_P) ; also on sheet 3
PCIE2_CLKREQ: J2.221(SDMMC3_DAT1) ; also on sheet 3
PCIE2_RST: J2.219(SDMMC3_DAT0) ; also on sheet 3
PCIE2_RX0_N: J2.40(CSI_D_D0_N) ; also on sheet 3
PCIE2_RX0_P: J2.42(CSI_D_D0_P) ; also on sheet 3
PCIE2_RX1_N: J2.58(CSI_C_D1_N) ; also on sheet 3
PCIE2_RX1_P: J2.60(CSI_C_D1_P) ; also on sheet 3
PCIE2_TX0_N: J2.46(CSI_C_D0_N) ; also on sheet 3
PCIE2_TX0_P: J2.48(CSI_C_D0_P) ; also on sheet 3
PCIE2_TX1_N: J2.64(CSI_D_D1_N) ; also on sheet 3
PCIE2_TX1_P: J2.66(CSI_D_D1_P) ; also on sheet 3
PCIE3_CLK_N: J2.227(SDMMC3_CMD) ; also on sheet 3
PCIE3_CLK_P: J2.229(SDMMC3_CLK) ; also on sheet 3
PCIE3_CLKREQ: J2.225(SDMMC3_DAT3) ; also on sheet 3
PCIE3_RST: J2.223(SDMMC3_DAT2) ; also on sheet 3
PCIE_WAKE: J2.179(PEX_WAKE) ; also on sheet 3 4 5
PWR_LED_CTRL: J2.127(GPIO04) ; also on sheet 1 21
SNN_DP0_AUX_N: J2.90(DP_AUX_CH0_N)
SNN_DP0_AUX_P: J2.92(DP_AUX_CH0_P)
SNN_DP0_HPD: J2.88(DP0_HPD)
SNN_DSI_CLK_N: J2.76(DSI_A_CLK_N)
SNN_DSI_CLK_P: J2.78(DSI_A_CLK_P)
SNN_DSI_D0_N: J2.70(DSI_A_D0_N)
SNN_DSI_D0_P: J2.72(DSI_A_D0_P)
SNN_DSI_D1_N: J2.82(DSI_A_D1_N)
SNN_DSI_D1_P: J2.84(DSI_A_D1_P)
SPI0_CS0: J2.95(SPI1_CS0) ; also on sheet 2
SPI0_CS1: J2.97(SPI1_CS1) ; also on sheet 2
SPI0_MISO: J2.93(SPI1_MISO) ; also on sheet 2
SPI0_MOSI: J2.89(SPI1_MOSI) ; also on sheet 2
SPI0_SCK: J2.91(SPI1_SCK) ; also on sheet 2
SPI1_CS0: J2.110(SPI2_CS0) ; also on sheet 2
SPI1_CS1: J2.112(SPI2_CS1) ; also on sheet 2
SPI1_MISO: J2.108(SPI2_MISO) ; also on sheet 2
SPI1_MOSI: J2.104(SPI2_MOSI) ; also on sheet 2
SPI1_SCK: J2.106(SPI2_SCK) ; also on sheet 2
SUSCLK_32KHZ: J2.210(CLK_32K_OUT) U1.2(A)
USB0_AP_N: J2.109(USB0_DN) ; also on sheet 12
USB0_AP_P: J2.111(USB0_DP) ; also on sheet 12
USB0_VBUS_DET*: J2.87(GPIO00) ; also on sheet 12
USB1_AP_N: J2.115(USB1_DN) ; also on sheet 11
USB1_AP_P: J2.117(USB1_DP) ; also on sheet 11
USB2_AP_N: J2.121(USB2_DN) ; also on sheet 5
USB2_AP_P: J2.123(USB2_DP) ; also on sheet 5
USBSS0_RX_N: C5.1 J2.161(PEX_RX6_N)
USBSS0_RX_P: C4.1 J2.163(PEX_RX6_P)
USBSS0_TX_HUB_N: C5.2 ; also on sheet 11
USBSS0_TX_HUB_P: C4.2 ; also on sheet 11
USBSS0_TX_N: J2.166(PEX_TX6_N) ; also on sheet 11
USBSS0_TX_P: J2.168(PEX_TX6_P) ; also on sheet 11
USBSS1_RX_N: J2.39(EDP_TXD0_N) ; also on sheet 12
USBSS1_RX_P: J2.41(EDP_TXD0_P) ; also on sheet 12
USBSS1_TX_N: J2.45(EDP_TXD1_N) ; also on sheet 12
USBSS1_TX_P: J2.47(EDP_TXD1_P) ; also on sheet 12
USBSS2_RX_N: J2.51(EDP_TXD2_N) TP101.1
USBSS2_RX_P: J2.53(EDP_TXD2_P) TP100.1
USBSS2_TX_N: J2.57(EDP_TXD3_N) TP103.1
USBSS2_TX_P: J2.59(EDP_TXD3_P) TP102.1
W_DISABLE1_CTRL: J2.128(GPIO05) ; also on sheet 5

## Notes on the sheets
sheet 18
- A
- B
- C
- D
- E
- F
- G
- H
- DC JACK POWER PATH
- 1
- 1
- RESERVED FOR POE
- BACKPOWER
- 2
- 2
- VOLTAGE:9V-20V
- 3
- 3
- 4
- 4
- 5
- 5
- NVIDIA CORPORATION
- 2701 SAN TOMAS EXPRESSWAY
- SANTA CLARA, CA 95050, USA
- ASSEMBLY
- <ASSEMBLY_DESCRIPTION>
- PAGE DETAIL
- DC JACK
- 600-13768-BASE-400
- NV_PN
- ALL NVIDIA DESIGN SPECIFICATIONS, REFERENCE SPECIFICATIONS, REFERENCE BOARDS, FILES, DRAWINGS, DIAGNOSTICS, LISTS AND OTHER DOCUMENTS OR INFORMATION (TOGETHER AND SEPARATELY, 'MATERIALS') ARE BEING PROVIDED 'AS IS'. THE MATERIALS MAY
- P3768-A04
- 7 OF 25
- CONTAIN KNOWN AND UNKNOWN VIOLATIONS OR DEVIATIONS OF INDUSTRY STANDARDS AND SPECIFICATIONS. NVIDIA MAKES NO WARRANTIES, EXPRESSED, IMPLIED, STATUTORY OR OTHERWISE WITH RESPECT TO THE MATERIALS OR OTHERWISE, AND EXPRESSLY DISCLAIMS ALL
- PCB REV
- PAGE
- IMPLIED WARRANTIES INCLUDING, WITHOUT LIMITATION, THE WARRANTIES OF DESIGN, OF NONINFRINGEMENT, MERCHANTABILITY OR FITNESS FOR A PARTICULAR PURPOSE, OR ARISING FROM A COURSE OF DEALING, TRADE USAGE, TRADE PRACTICE, OR INDUSTRY STANDARDS.
- BOM REV
- A
- DATE
- 27-FEB-2023
- A
- B
- C
- D
- E
- F
- G
- H
sheet 19
- A
- B
- C
- D
- E
- F
- G
- H
- DP, USBSS and PEX
- 1
- 1
- M.2M (x4 NVMe)
- 2
- 2
- USB Type-C
- place near R215
- place near R214
- place near C73
- place near C75
- 3
- 3
- DisplayPort
- USB Type-A (Hub)
- M.2E (Wifi/BT)
- 4
- 4
- 5
- 5
- NVIDIA CORPORATION
- 2701 SAN TOMAS EXPRESSWAY
- SANTA CLARA, CA 95050, USA
- ASSEMBLY
- <ASSEMBLY_DESCRIPTION>
- PAGE DETAIL
- SODIMM Connector 3/3
- 600-13768-BASE-400
- NV_PN
- ALL NVIDIA DESIGN SPECIFICATIONS, REFERENCE SPECIFICATIONS, REFERENCE BOARDS, FILES, DRAWINGS, DIAGNOSTICS, LISTS AND OTHER DOCUMENTS OR INFORMATION (TOGETHER AND SEPARATELY, 'MATERIALS') ARE BEING PROVIDED 'AS IS'. THE MATERIALS MAY
- P3768-A04
- 6 OF 25
- CONTAIN KNOWN AND UNKNOWN VIOLATIONS OR DEVIATIONS OF INDUSTRY STANDARDS AND SPECIFICATIONS. NVIDIA MAKES NO WARRANTIES, EXPRESSED, IMPLIED, STATUTORY OR OTHERWISE WITH RESPECT TO THE MATERIALS OR OTHERWISE, AND EXPRESSLY DISCLAIMS ALL
- PCB REV
- PAGE
- IMPLIED WARRANTIES INCLUDING, WITHOUT LIMITATION, THE WARRANTIES OF DESIGN, OF NONINFRINGEMENT, MERCHANTABILITY OR FITNESS FOR A PARTICULAR PURPOSE, OR ARISING FROM A COURSE OF DEALING, TRADE USAGE, TRADE PRACTICE, OR INDUSTRY STANDARDS.
- BOM REV
- A
- DATE
- 27-FEB-2023
- A
- B
- C
- D
- E
- F
- G
- H
sheet 20
- A
- B
- C
- D
- E
- F
- G
- H
- GPIOs, USB2.0, I2S, SPI, GBe and CSI
- 1
- 1
- Debug USB
- USB Type-A (Hub)
- M.2E BT
- CAM0 FPC
- 40pin GPIO HDR
- 2
- 2
- M.2E BT
- CAM1 FPC
- Ethernet RJ45
- 3
- 3
- M.2M (x2 NVMe)
- PCIe2/3 Sideband
- 4
- 4
- Camera FPC
- USB3.1 HUB
- 40pin GPIO HDR
- 5
- 5
- NVIDIA CORPORATION
- 2701 SAN TOMAS EXPRESSWAY
- SANTA CLARA, CA 95050, USA
- ASSEMBLY
- <ASSEMBLY_DESCRIPTION>
- PAGE DETAIL
- SODIMM Connector 2/3
- 600-13768-BASE-400
- NV_PN
- ALL NVIDIA DESIGN SPECIFICATIONS, REFERENCE SPECIFICATIONS, REFERENCE BOARDS, FILES, DRAWINGS, DIAGNOSTICS, LISTS AND OTHER DOCUMENTS OR INFORMATION (TOGETHER AND SEPARATELY, 'MATERIALS') ARE BEING PROVIDED 'AS IS'. THE MATERIALS MAY
- P3768-A04
- 5 OF 25
- CONTAIN KNOWN AND UNKNOWN VIOLATIONS OR DEVIATIONS OF INDUSTRY STANDARDS AND SPECIFICATIONS. NVIDIA MAKES NO WARRANTIES, EXPRESSED, IMPLIED, STATUTORY OR OTHERWISE WITH RESPECT TO THE MATERIALS OR OTHERWISE, AND EXPRESSLY DISCLAIMS ALL
- PCB REV
- PAGE
- IMPLIED WARRANTIES INCLUDING, WITHOUT LIMITATION, THE WARRANTIES OF DESIGN, OF NONINFRINGEMENT, MERCHANTABILITY OR FITNESS FOR A PARTICULAR PURPOSE, OR ARISING FROM A COURSE OF DEALING, TRADE USAGE, TRADE PRACTICE, OR INDUSTRY STANDARDS.
- BOM REV
- A
- DATE
- 27-FEB-2023
- A
- B
- C
- D
- E
- F
- G
- H
